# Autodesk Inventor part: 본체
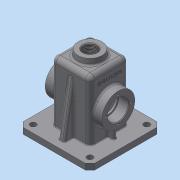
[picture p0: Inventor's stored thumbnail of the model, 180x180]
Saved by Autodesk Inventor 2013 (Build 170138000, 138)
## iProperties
Created: 2018-10
Part Number: 본체
Material: 일반
Document SubType Name: Modeling
Designer: Administrator
Density: 1 g/cm^3
Author: Administrator
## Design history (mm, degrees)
sketch "스케치1"
  geometry: L1 (-32.5, -32.5)-(32.5, -32.5); L2 (32.5, -32.5)-(32.5, 32.5); L3 (32.5, 32.5)-(-32.5, 32.5); L4 (-32.5, 32.5)-(-32.5, -32.5); L5 (-32.5, -32.5)-(32.5, 32.5); L6 (32.5, -32.5)-(-32.5, 32.5); 1 further point
  constraints: 12 end point, 2 midpoint, 2 parallel, 1 horizontal, 1 perpendicular
  dimensions: "d0" = 65 distance of L3.end L2.end; "d1" = 65 distance of L2.end L1.end
extrude "돌출1" new body sketch "스케치1" stored distance "d2" = 110; taper "d3" = 0 deg
feature "쉘1" dims "d4" = 5
sketch "스케치2"
  geometry: L1 (-32.5, -32.5)-(32.5, -32.5) reference; L2 (32.5, -32.5)-(32.5, 32.5) reference; L3 (32.5, 32.5)-(-32.5, 32.5) reference; L4 (-32.5, 32.5)-(-32.5, -32.5) reference; L5 (-60, -60)-(60, -60); L6 (60, -60)-(60, 60); L7 (60, 60)-(-60, 60); L8 (-60, 60)-(-60, -60); L9 (-60, -60)-(60, 60); L10 (60, -60)-(-60, 60); 1 further point
  constraints: 12 end point, 2 midpoint, 2 parallel, 1 horizontal, 1 perpendicular
  dimensions: "d5" = 120 distance of L7.end L6.end; "d6" = 120 distance of L6.end L5.end
extrude "돌출2" join sketch "스케치2" distance "d7" = 10; taper "d8" = 0 deg
node "작업 평면1"
sketch "스케치3"
  geometry: C1 r 20 at (0, 0); 1 further point
  constraints: 1 centre point, 1 coincident
  dimensions: "d10" = 40 diameter of C1
extrude "돌출3" join sketch "스케치3" stored distance "d11" = 10; taper "d12" = 7 deg
fillet "모깎기1" dims "d13" = 8
node "작업 평면2"
sketch "스케치5"
  geometry: C1 r 27.5 at (47, 24.5); 1 further point
  constraints: 1 centre point, 1 coincident
  dimensions: "d15" = 55 diameter of C1
extrude "돌출4" join sketch "스케치5" stored distance "d16" = 10; taper "d17" = 0 deg
sketch "스케치6"
  geometry: C1 r 27.5 at (0, 0) reference
hole "구멍1" sketch "스케치6" at (0, 0) diameter "d18" = 30; stored, may be unused: countersink angle "d22" = 90 deg, drill point angle "d24" = 0 deg; dims "d19" = 6, "d20" = 35, "d21" = 17, "d23" = 8
sketch "스케치7"
  geometry: L1 (0, 0)-(-21, 0); C1 r 27.5 at (0, 0) reference; 1 further point
  constraints: 2 end point, 1 coincident, 1 horizontal
  dimensions: "d25" = 21 distance of L1.start L1.end
hole "구멍2" sketch "스케치7" at (-21, 0) diameter "d26" = 3.459; stored, may be unused: countersink angle "d30" = 90 deg, drill point angle "d32" = 118 deg; dims "d27" = 8, "d28" = 35, "d29" = 17, "d31" = 10
fillet "모깎기2" dims "d36" = 3
fillet "모깎기3" dims "d37" = 3
sketch "스케치8"
  geometry: C1 r 20 at (0, 0) reference
hole "구멍3" sketch "스케치8" at (0, 0) diameter "d38" = 22.835; stored, may be unused: countersink angle "d42" = 90 deg, drill point angle "d44" = 118 deg; dims "d39" = 8, "d40" = 35, "d41" = 17, "d43" = 10
sketch "스케치9"
  geometry: L1 (42.358, -13)-(48, -45); L2 (60, -45)-(-60, -45) reference; L3 (60, -55)-(60, -45) reference; 1 further point
  constraints: 2 end point, 1 point on line
  dimensions: "d46" = 10 deg angle of L1 L3; "d47" = 12 distance from line of L1.end L3
feature "리브1" sketch "스케치9" dims "d48" = 1, "d49" = 10, "d50" = 0, "d51" = 0, "d52" = 1, "d53" = 1
sketch "스케치10"
  geometry: L1 (42.5, -31)-(42.5, -45); L2 (27.5, 50)-(27.5, -55) reference; L3 (30.5, -15)-(30.5, -17.5) reference; L4 (30.5, -17.5)-(47.5, -17.5) reference; L5 (47.5, -17.5)-(47.5, -19.271) reference; L6 (47.5, -19.271)-(37.5, -19.271) reference; L7 (37.5, -19.271)-(36.461, -21) reference; L8 (36.461, -21)-(37.5, -22.73) reference; L9 (37.5, -22.73)-(47.5, -22.73) reference; L10 (47.5, -22.73)-(47.5, -27.5) reference; L11 (47.5, -27.5)-(35.5, -27.5) reference; L12 (32.5, -30.5)-(32.5, -45) reference; L13 (32.5, -45)-(60, -45) reference; L14 (60, -45)-(60, -55) reference; L15 (60, -55)-(27.5, -55) reference; L16 (27.5, -55)-(27.5, -15) reference; L17 (27.5, -15)-(30.5, -15) reference; L18 (36.461, 21)-(37.5, 19.271) reference; L19 (37.5, 19.271)-(47.5, 19.271) reference; L20 (47.5, 19.271)-(47.5, 17.5) reference; L21 (47.5, 17.5)-(30.5, 17.5) reference; L22 (30.5, 17.5)-(30.5, 15) reference; L23 (30.5, 15)-(27.5, 15) reference; L24 (27.5, 15)-(27.5, 50) reference; L25 (27.5, 50)-(11.418, 50) reference; L26 (11.418, 50)-(11.418, 65) reference; L27 (11.418, 65)-(20, 65) reference; L28 (20, 65)-(21.228, 55) reference; L29 (21.228, 55)-(24.5, 55) reference; L30 (32.5, 47)-(32.5, 30.5) reference; L31 (35.5, 27.5)-(47.5, 27.5) reference; L32 (47.5, 27.5)-(47.5, 22.73) reference; L33 (47.5, 22.73)-(37.5, 22.73) reference; L34 (37.5, 22.73)-(36.461, 21) reference; L35 (-30.5, -17.5)-(-30.5, -15) reference; L36 (-30.5, -15)-(-27.5, -15) reference; L37 (-27.5, -15)-(-27.5, -55) reference; L38 (-27.5, -55)-(-60, -55) reference; L39 (-60, -55)-(-60, -45) reference; L40 (-60, -45)-(-32.5, -45) reference; L41 (-32.5, -45)-(-32.5, -30.5) reference; L42 (-35.5, -27.5)-(-47.5, -27.5) reference; L43 (-47.5, -27.5)-(-47.5, -22.73) reference; L44 (-47.5, -22.73)-(-37.5, -22.73) reference; L45 (-37.5, -22.73)-(-36.461, -21) reference; L46 (-36.461, -21)-(-37.5, -19.271) reference; L47 (-37.5, -19.271)-(-47.5, -19.271) reference; L48 (-47.5, -19.271)-(-47.5, -17.5) reference; L49 (-47.5, -17.5)-(-30.5, -17.5) reference; L50 (-30.5, 15)-(-30.5, 17.5) reference; L51 (-30.5, 17.5)-(-47.5, 17.5) reference; L52 (-47.5, 17.5)-(-47.5, 19.271) reference; L53 (-47.5, 19.271)-(-37.5, 19.271) reference; L54 (-37.5, 19.271)-(-36.461, 21) reference; L55 (-36.461, 21)-(-37.5, 22.73) reference; L56 (-37.5, 22.73)-(-47.5, 22.73) reference; L57 (-47.5, 22.73)-(-47.5, 27.5) reference; L58 (-47.5, 27.5)-(-35.5, 27.5) reference; L59 (-32.5, 30.5)-(-32.5, 47) reference; L60 (-24.5, 55)-(-21.228, 55) reference; L61 (-21.228, 55)-(-20, 65) reference; L62 (-20, 65)-(-11.418, 65) reference; L63 (-11.418, 65)-(-11.418, 50) reference; L64 (-11.418, 50)-(-27.5, 50) reference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; A1 r 3 centre (35.5, -30.5) between (35.5, -27.5) and (32.5, -30.5) reference; A2 r 8 centre (24.5, 47) between (32.5, 47) and (24.5, 55) reference; A3 r 3 centre (35.5, 30.5) between (32.5, 30.5) and (35.5, 27.5) reference; A4 r 3 centre (-35.5, -30.5) between (-32.5, -30.5) and (-35.5, -27.5) reference; A5 r 3 centre (-35.5, 30.5) between (-35.5, 27.5) and (-32.5, 30.5) reference; A6 r 8 centre (-24.5, 47) between (-24.5, 55) and (-32.5, 47) reference; 1 further point
  constraints: 2 end point, 1 point on line, 1 vertical
  dimensions: "d54" = 15 distance between parallel lines of L1 L2
feature "리브2" sketch "스케치10" dims "d55" = 1, "d56" = 6, "d57" = 0, "d58" = 0, "d59" = 1, "d60" = 1
chamfer "모따기1" distance "d61" = 8; stored, may be unused: second distance "d62" = 2, angle "d63" = 45 deg
sketch "스케치11"
  geometry: C1 r 5 at (-47.5, 47.5); 1 further point
  constraints: 1 centre point
  dimensions: "d64" = 10 diameter of C1; "d65" = 47.5 horizontal distance of C1.centre point (0, 0); "d66" = 47.5 horizontal distance of C1.centre point (0, 0)
extrude "돌출5" cut sketch "스케치11" stored distance "d67" = 10; taper "d68" = 0 deg
fillet "모깎기4" dims "d72" = 3
fillet "모깎기5" dims "d73" = 0.3
fillet "모깎기6" dims "d74" = 3
chamfer "모따기2" distance "d75" = 1; stored, may be unused: second distance "d76" = 2, angle "d77" = 45 deg
sketch "스케치12"
  geometry: L1 (0, -8)-(92, -8) reference; L2 (-18, 4.5)-(-18, 44.5) reference; 1 further point
  constraints: 1 other
  dimensions: "d78" = 32.5 distance from line of L1 point (8, 24.5); "d79" = 26 distance from line of point (8, 24.5) L2
feature "엠보싱1" sketch "스케치12" dims "d5" = 120, "d6" = 120, "d80" = 0.5, "d81" = 0
fillet "모깎기11" dims "d86" = 3
fillet "모깎기12" dims "d87" = 3
fillet "모깎기13" dims "d88" = 1
node "솔리드1"
pattern_circular "원형 패턴1" dims angle "d34" = 360 deg
mirror "대칭1"
mirror "대칭2"
mirror "대칭3"
pattern_linear "직사각형 패턴1" dims "d71" = 95
mirror "대칭4"
node "절단 모서리 투영1"
other parameters: "d14" = 15
